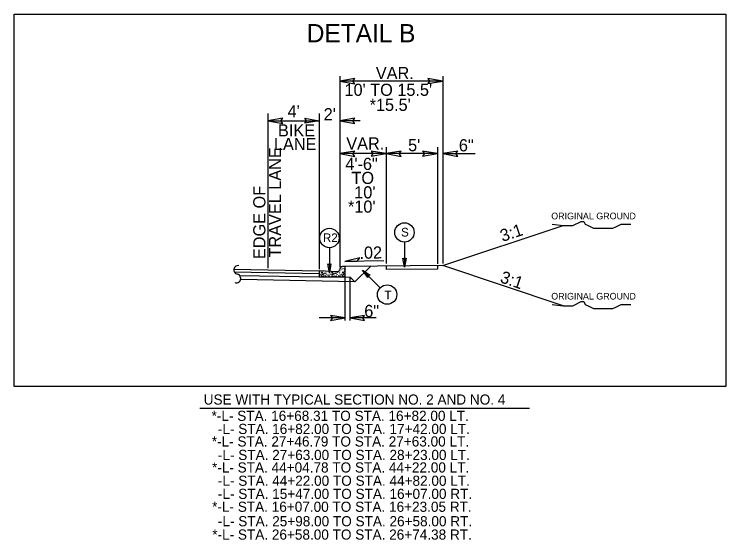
# Model space of a CAD drawing. Extents: x 957297 to 961629, y 830661 to 840840.
# Drawn here: x 961172.6 to 961628.9, y 838867.9 to 839205.1 of the extents above; entities that cross this region are included whole.
import ezdxf

# ---------------------------------------------------------------- set-up
doc = ezdxf.new("R2010")
doc.units = 0
for name, color, linetype in [('Old_Level_1', 7, 'Continuous'), ('Old_Level_11', 7, 'Continuous'), ('Old_Level_21', 7, 'Continuous'), ('Old_Level_3', 7, 'Continuous'), ('Prop Dimension Text', 7, 'Continuous'), ('Typical ID Circle CELL', 7, 'Continuous'), ('Typical Terminator CELL', 7, 'Continuous'), ('Typical Text ID Circle CELL', 7, 'Continuous')]:
    doc.layers.add(name, color=color, linetype=linetype)

msp = doc.modelspace()

# ---------------------------------------------------------------- linework, layer by layer
at = {"layer": 'Old_Level_1'}
for p, q in [((961381.36, 839165.36), (961381.36, 839042.81)), ((961447.4, 839162.21), (961381.36, 839162.21)), ((961447.4, 839165.36), (961447.4, 839045.27)), ((961335.15, 839141.41), (961335.15, 839042.11)), ((961368.15, 839141.41), (961368.15, 839041.61)), ((961335.15, 839136.79), (961368.15, 839136.79)), ((961394.42, 839136.79), (961381.36, 839136.79)), ((961411.08, 839119.8), (961411.08, 839045.27)), ((961444.1, 839119.8), (961444.1, 839044.9)), ((961411.08, 839115.64), (961381.36, 839115.64)), ((961444.1, 839115.64), (961411.08, 839115.64)), ((961447.4, 839115.64), (961468.07, 839115.64)), ((961447.4, 839043.79), (961524.59, 839069.52)), ((961447.4, 839043.79), (961384.44, 839043.16)), ((961409.65, 839046.93), (961384.54, 839046.43)), ((961391.09, 839033.39), (961401.02, 839043.32)), ((961411.08, 839043.42), (961411.08, 839041.24)), ((961444.1, 839043.76), (961444.1, 839041.58)), ((961524.59, 839018.06), (961447.4, 839043.79)), ((961313.46, 839041.61), (961368.15, 839040.51)), ((961313.65, 839039.88), (961368.15, 839038.78)), ((961444.1, 839041.58), (961411.08, 839041.24)), ((961316.98, 839037.56), (961368.15, 839036.52)), ((961317.8, 839035.05), (961391.1, 839033.57)), ((961384.73, 839036.53), (961388.03, 839036.46)), ((961384.73, 839008.63), (961384.73, 839036.25)), ((961388.03, 839036.46), (961391.09, 839033.39)), ((961388.03, 839008.63), (961388.03, 839036.25)), ((961384.73, 839010.21), (961368.13, 839010.21)), ((961404.63, 839010.21), (961388.03, 839010.21)), ((961291.65, 838952.46), (961503.06, 838952.46))]:
    msp.add_line(p, q, dxfattribs=at)
msp.add_lwpolyline([(961172.59, 839205.09), (961628.87, 839205.09), (961628.87, 838966.28), (961172.59, 838966.28)], close=True, dxfattribs=at)
for centre, start, end in [((961316.21, 839041.03), 79.4545, 256.8065), ((961315.03, 839035.53), 248.3355, 78.8593)]:
    msp.add_arc(centre, 2.81, start, end, dxfattribs=at)
at = {"layer": 'Old_Level_11'}
for p, q in [((961394.28, 839048.84), (961384.54, 839046.43)), ((961392.55, 839046.59), (961394.28, 839048.84)), ((961384.54, 839046.43), (961392.55, 839046.59))]:
    msp.add_line(p, q, dxfattribs=at)
for points in [[(961390.97, 839163.86), (961381.36, 839162.21), (961391.03, 839160.49), (961389.8, 839162.21)], [(961437.79, 839160.55), (961447.4, 839162.21), (961437.74, 839163.92), (961438.96, 839162.21)], [(961344.76, 839138.44), (961335.15, 839136.79), (961344.82, 839135.07), (961343.59, 839136.79)], [(961390.97, 839138.44), (961381.36, 839136.79), (961391.03, 839135.07), (961389.8, 839136.79)], [(961390.97, 839117.29), (961381.36, 839115.64), (961391.03, 839113.92), (961389.8, 839115.64)], [(961401.47, 839113.98), (961411.08, 839115.64), (961401.42, 839117.34), (961402.64, 839115.64)], [(961420.69, 839117.29), (961411.08, 839115.64), (961420.75, 839113.92), (961419.52, 839115.64)], [(961434.49, 839113.98), (961444.1, 839115.64), (961434.44, 839117.34), (961435.66, 839115.64)], [(961457.01, 839117.29), (961447.4, 839115.64), (961457.07, 839113.92), (961455.84, 839115.64)]]:
    msp.add_lwpolyline(points, close=True, dxfattribs=at)
at = {"layer": 'Old_Level_21'}
for points in [[(961517.49, 839070.4), (961524.59, 839069.52), (961526.36, 839069.52), (961529.02, 839069.52), (961530.8, 839069.52), (961532.57, 839070.4), (961534.35, 839071.3), (961536.12, 839072.18), (961537.89, 839072.18), (961538.79, 839070.4), (961540.55, 839069.52), (961542.33, 839068.62), (961544.1, 839067.75), (961545.88, 839067.75), (961547.64, 839067.75), (961549.42, 839067.75), (961551.19, 839067.75), (961552.97, 839067.75), (961554.74, 839067.75), (961556.52, 839067.75), (961558.29, 839068.62), (961560.05, 839069.52), (961561.82, 839070.4), (961564.5, 839070.4), (961566.27, 839070.4), (961568.04, 839070.4)], [(961517.49, 839018.94), (961524.59, 839018.06), (961526.36, 839018.06), (961529.02, 839018.06), (961530.8, 839018.06), (961532.57, 839018.94), (961534.35, 839019.83), (961536.12, 839020.71), (961537.89, 839020.71), (961538.79, 839018.94), (961540.55, 839018.06), (961542.33, 839017.16), (961544.1, 839016.29), (961545.88, 839016.29), (961547.64, 839016.29), (961549.42, 839016.29), (961551.19, 839016.29), (961552.97, 839016.29), (961554.74, 839016.29), (961556.52, 839016.29), (961558.29, 839017.16), (961560.05, 839018.06), (961561.82, 839018.94), (961564.5, 839018.94), (961566.27, 839018.94), (961568.04, 839018.94)]]:
    msp.add_lwpolyline(points, dxfattribs=at)
at = {"layer": 'Old_Level_3'}
for p, q in [((961384.44, 839043.16), (961383.07, 839043.16)), ((961379.69, 839039.93), (961368.15, 839040.51)), ((961368.15, 839040.51), (961368.15, 839036.53)), ((961369.41, 839039.58), (961369.99, 839039.61)), ((961369.99, 839039.03), (961369.41, 839039.58)), ((961369.99, 839039.61), (961369.99, 839039.03)), ((961371.67, 839038.97), (961372.51, 839039.2)), ((961372.41, 839038.72), (961371.67, 839038.97)), ((961372.51, 839039.2), (961372.41, 839038.72)), ((961376.14, 839039.58), (961376.72, 839039.61)), ((961376.72, 839039.03), (961376.14, 839039.58)), ((961376.72, 839039.61), (961376.72, 839039.03)), ((961378.41, 839038.97), (961379.23, 839039.2)), ((961379.14, 839038.72), (961378.41, 839038.97)), ((961379.23, 839039.2), (961379.14, 839038.72)), ((961379.69, 839039.93), (961379.69, 839039.93)), ((961381.39, 839040.97), (961381.24, 839041)), ((961381.28, 839041.11), (961381.39, 839040.97)), ((961382.87, 839039.58), (961383.45, 839039.61)), ((961383.45, 839039.03), (961382.87, 839039.58)), ((961383.45, 839039.61), (961383.45, 839039.03)), ((961384.73, 839039.84), (961384.73, 839042.87)), ((961384.73, 839036.53), (961384.73, 839039.84)), ((961368.15, 839036.53), (961384.73, 839036.53)), ((961369.62, 839037.56), (961369.44, 839036.94)), ((961369.44, 839036.94), (961370.08, 839036.91)), ((961370.08, 839036.91), (961369.62, 839037.56)), ((961372.35, 839037.25), (961371.79, 839036.85)), ((961371.79, 839036.85), (961372.69, 839036.64)), ((961372.69, 839036.64), (961372.35, 839037.25)), ((961376.35, 839037.56), (961376.17, 839036.94)), ((961376.17, 839036.94), (961376.81, 839036.91)), ((961376.81, 839036.91), (961376.35, 839037.56)), ((961379.08, 839037.25), (961378.53, 839036.85)), ((961378.53, 839036.85), (961379.42, 839036.64)), ((961379.42, 839036.64), (961379.08, 839037.25)), ((961383.07, 839037.56), (961382.9, 839036.94)), ((961382.9, 839036.94), (961383.54, 839036.91)), ((961383.54, 839036.91), (961383.07, 839037.56))]:
    msp.add_line(p, q, dxfattribs=at)
for centre in [(961368.36, 839039.12), (961368.64, 839040.23), (961369.65, 839038.53), (961370.42, 839038.44), (961370.58, 839040.04), (961371.12, 839038.84), (961371.83, 839039.43), (961373.27, 839039.58), (961374.35, 839039.18), (961374.38, 839038.38), (961375.09, 839039.12), (961376.38, 839038.53), (961377.15, 839038.44), (961377.85, 839038.84), (961378.56, 839039.43), (961380, 839039.58), (961380.99, 839040.2), (961381.08, 839039.18), (961381.11, 839038.38), (961381.76, 839041.03), (961381.79, 839042.32), (961381.82, 839039.12), (961382.09, 839040.23), (961382.74, 839041.52), (961382.89, 839042.44), (961383.11, 839038.53), (961383.76, 839042.07), (961383.88, 839038.44), (961383.91, 839041.33), (961384.03, 839040.04), (961384.58, 839038.84), (961384.67, 839041.43), (961368.7, 839037.65), (961368.85, 839038.2), (961369.9, 839037.99), (961370.58, 839036.91), (961371.01, 839037.77), (961371.09, 839036.66), (961371.31, 839037.96), (961371.4, 839037.43), (961372.35, 839037.96), (961373, 839038.23), (961373.95, 839037.34), (961374.47, 839038.11), (961374.63, 839037.19), (961375.43, 839037.65), (961375.58, 839038.2), (961376.63, 839037.99), (961377.3, 839036.91), (961377.73, 839037.77), (961377.82, 839036.66), (961378.03, 839037.96), (961378.13, 839037.43), (961379.08, 839037.96), (961379.73, 839038.23), (961380.68, 839037.34), (961381.2, 839038.11), (961381.36, 839037.19), (961382.16, 839037.65), (961382.31, 839038.2), (961383.36, 839037.99), (961384.03, 839036.91), (961384.46, 839037.77), (961384.55, 839036.66)]:
    msp.add_circle(centre, 0.0432, dxfattribs=at)
for centre, radius, start, end in [((961383.07, 839041.5), 1.66, 90, 178.9266), ((961384.44, 839042.87), 0.287, 0, 90), ((961384.55, 839043.09), 0.0432, 169.6531, 280.3469), ((961374.26, 839040.2), 0.0432, 164.1199, 10.1626), ((961377.3, 839040.04), 0.0432, 162.062, 12.2205), ((961379.78, 839041.57), 1.64, 267.1376, 358.9266), ((961384.76, 839037.96), 0.0432, 150.4173, 209.5827)]:
    msp.add_arc(centre, radius, start, end, dxfattribs=at)
at = {"layer": 'Typical ID Circle CELL'}
for p, q in [((961422.83, 839058.88), (961422.83, 839042.79)), ((961374.72, 839055.33), (961374.72, 839039.24)), ((961407.32, 839029.62), (961395.95, 839041))]:
    msp.add_line(p, q, dxfattribs=at)
for centre in [(961422.83, 839065.1), (961374.72, 839061.55), (961411.72, 839025.22)]:
    msp.add_circle(centre, 6.23, dxfattribs=at)
at = {"layer": 'Typical Terminator CELL'}
for points in [[(961358.93, 839138.37), (961368.15, 839136.79), (961358.88, 839135.15), (961360.06, 839136.79)], [(961423.82, 839048.55), (961422.83, 839042.79), (961421.8, 839048.59), (961422.83, 839047.85)], [(961375.71, 839045), (961374.72, 839039.24), (961373.69, 839045.03), (961374.72, 839044.3)], [(961399.32, 839036.22), (961395.95, 839041), (961400.77, 839037.62), (961399.52, 839037.42)], [(961375.5, 839008.63), (961384.73, 839010.21), (961375.45, 839011.85), (961376.63, 839010.21)], [(961397.25, 839011.8), (961388.03, 839010.21), (961397.3, 839008.57), (961396.12, 839010.21)]]:
    msp.add_lwpolyline(points, close=True, dxfattribs=at)

# ---------------------------------------------------------------- texts
at = {"layer": 'Old_Level_1'}
for s, height, p in [('DETAIL B', 11.716, (961360.22, 839187.07)), ('USE WITH TYPICAL SECTION NO. 2 AND NO. 4', 6.5088, (961294.09, 838954.65)), ('*-L- STA. 16+68.31 TO STA. 16+82.00 LT.', 6.5088, (961299.15, 838944.19)), ('-L- STA. 16+82.00 TO STA. 17+42.00 LT.', 6.5088, (961303.19, 838935.79)), ('*-L- STA. 27+46.79 TO STA. 27+63.00 LT.', 6.5088, (961299.29, 838927.76)), ('-L- STA. 27+63.00 TO STA. 28+23.00 LT.', 6.5088, (961303.19, 838919.11)), ('*-L- STA. 44+04.78 TO STA. 44+22.00 LT.', 6.5088, (961299.42, 838911.08)), ('-L- STA. 44+22.00 TO STA. 44+82.00 LT.', 6.5088, (961303.19, 838902.55)), ('-L- STA. 15+47.00 TO STA. 16+07.00 RT.', 6.5088, (961303.19, 838894.14)), ('*-L- STA. 16+07.00 TO STA. 16+23.05 RT.', 6.5088, (961299.51, 838885.86)), ('-L- STA. 25+98.00 TO STA. 26+58.00 RT.', 6.5088, (961303.19, 838876.58)), ('*-L- STA. 26+58.00 TO STA. 26+74.38 RT.', 6.5088, (961299.6, 838868.02))]:
    msp.add_text(s, height=height, dxfattribs=at).set_placement(p)
at = {"layer": 'Old_Level_21'}
for p in [(961516.95, 839073.51), (961516.95, 839022.05)]:
    msp.add_text('ORIGINAL GROUND', height=4.2722, dxfattribs=at).set_placement(p)
at = {"layer": 'Old_Level_3'}
for s, height, p in [('VAR.', 7.801, (961404.46, 839163.45)), ("10' TO 15.5'", 7.8009, (961384.38, 839152.72)), ("*15.5'", 7.801, (961400.5, 839143.06)), ("4'", 7.801, (961347.88, 839138.92)), ("2'", 7.801, (961371.02, 839137.03)), ('BIKE', 7.801, (961341.72, 839126.67)), ('LANE', 7.801, (961339.13, 839117.92)), ('VAR.', 7.801, (961385.53, 839118.26)), ("5'", 7.801, (961425.17, 839117.2)), ('6"', 7.801, (961457.72, 839117.11)), ('4\'-6"', 7.801, (961384.92, 839105.16)), ('TO', 7.801, (961388.84, 839096.18)), ("10'", 7.801, (961390.63, 839086.93)), ("*10'", 7.801, (961386.62, 839077.78))]:
    msp.add_text(s, height=height, dxfattribs=at).set_placement(p)
for s, height, rotation, p in [('TRAVEL LANE', 7.8009, 90, (961343.75, 839049.01)), ('EDGE OF', 7.801, 90, (961333.66, 839048.01)), ('3:1', 7.801, 18.4348, (961485.7, 839058.97)), ('3:1', 7.801, 341.0454, (961483.64, 839033.28))]:
    msp.add_text(s, height=height, rotation=rotation, dxfattribs=at).set_placement(p)
at = {"layer": 'Prop Dimension Text'}
for s, rotation, p in [('.02', 1.1839, (961394.03, 839048.12)), ('6"', 0, (961397.05, 839010.81))]:
    msp.add_text(s, height=7.801, rotation=rotation, dxfattribs=at).set_placement(p)
at = {"layer": 'Typical Text ID Circle CELL'}
for s, height, p in [('S', 5.57, (961420.66, 839062.47)), ('R2', 5.572, (961370.52, 839058.92)), ('T', 5.57, (961410.02, 839022.24))]:
    msp.add_text(s, height=height, dxfattribs=at).set_placement(p)

doc.saveas('drawing.dxf')
